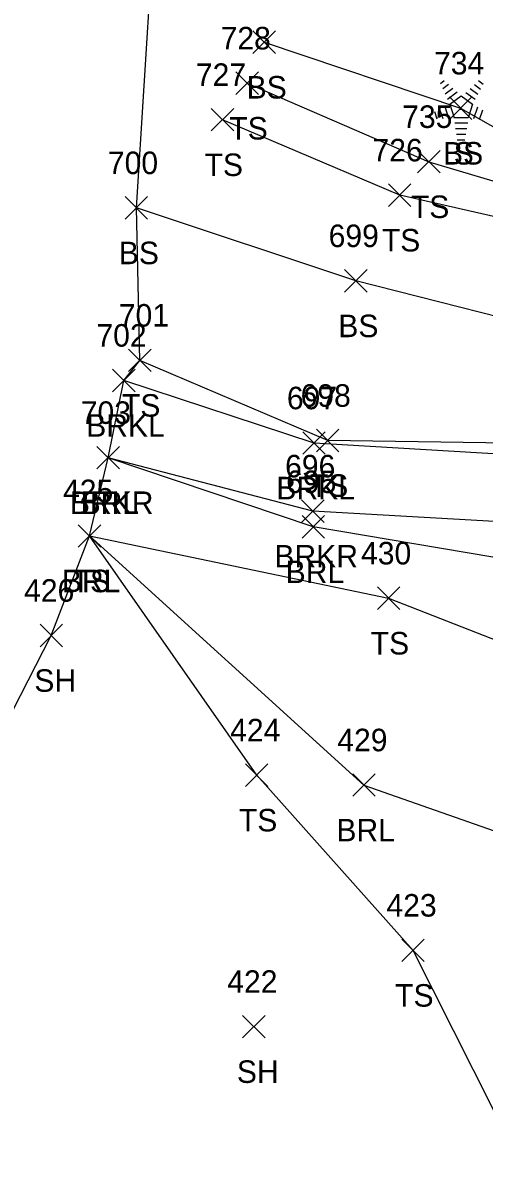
# Model space of a CAD drawing. Extents: x 1482574 to 1485769, y 580696 to 595649.
# Drawn here: x 1483551.5 to 1483592.5, y 584458.9 to 584560.7 of the extents above; entities that cross this region are included whole.
import ezdxf

# ---------------------------------------------------------------- set-up
doc = ezdxf.new("R2010")
doc.units = 0
for name, color, linetype in [('L_A', 7, 'Continuous'), ('L_I', 7, 'Continuous'), ('L_TIC', 7, 'Continuous'), ('LABL', 7, 'Continuous'), ('LAWE', 7, 'Continuous'), ('LELB', 7, 'Continuous'), ('LSOGP', 7, 'Continuous'), ('LTC', 7, 'Continuous')]:
    doc.layers.add(name, color=color, linetype=linetype)

msp = doc.modelspace()

# ---------------------------------------------------------------- linework, layer by layer
at = {"layer": 'L_TIC'}
for points in [[(1483571.91, 584558.01), (1483573.91, 584560.01)], [(1483573.91, 584558.01), (1483571.91, 584560.01)], [(1483570.4, 584554.37), (1483572.4, 584556.37)], [(1483572.4, 584554.37), (1483570.4, 584556.37)], [(1483589.37, 584552.15), (1483591.37, 584554.15)], [(1483591.37, 584552.15), (1483589.37, 584554.15)], [(1483568.2, 584551.13), (1483570.2, 584553.13)], [(1483570.2, 584551.13), (1483568.2, 584553.13)], [(1483586.54, 584547.4), (1483588.54, 584549.4)], [(1483588.54, 584547.4), (1483586.54, 584549.4)], [(1483583.96, 584544.43), (1483585.96, 584546.43)], [(1483585.96, 584544.43), (1483583.96, 584546.43)], [(1483560.55, 584543.3), (1483562.55, 584545.3)], [(1483562.55, 584543.3), (1483560.55, 584545.3)], [(1483580.06, 584536.82), (1483582.06, 584538.82)], [(1483582.06, 584536.82), (1483580.06, 584538.82)], [(1483560.86, 584529.76), (1483562.86, 584531.76)], [(1483562.86, 584529.76), (1483560.86, 584531.76)], [(1483559.44, 584527.98), (1483561.44, 584529.98)], [(1483561.44, 584527.98), (1483559.44, 584529.98)], [(1483576.34, 584522.42), (1483578.34, 584524.42)], [(1483578.34, 584522.42), (1483576.34, 584524.42)], [(1483577.56, 584522.64), (1483579.56, 584524.64)], [(1483579.56, 584522.64), (1483577.56, 584524.64)], [(1483558.05, 584521.12), (1483560.05, 584523.12)], [(1483560.05, 584521.12), (1483558.05, 584523.12)], [(1483558.05, 584521.12), (1483560.05, 584523.12)], [(1483560.05, 584521.12), (1483558.05, 584523.12)], [(1483576.23, 584516.37), (1483578.23, 584518.37)], [(1483578.23, 584516.37), (1483576.23, 584518.37)], [(1483556.39, 584514.17), (1483558.39, 584516.17)], [(1483558.39, 584514.17), (1483556.39, 584516.17)], [(1483556.39, 584514.17), (1483558.39, 584516.17)], [(1483558.39, 584514.17), (1483556.39, 584516.17)], [(1483576.28, 584514.98), (1483578.28, 584516.98)], [(1483578.28, 584514.98), (1483576.28, 584516.98)], [(1483582.97, 584508.64), (1483584.97, 584510.64)], [(1483584.97, 584508.64), (1483582.97, 584510.64)], [(1483552.99, 584505.33), (1483554.99, 584507.33)], [(1483554.99, 584505.33), (1483552.99, 584507.33)], [(1483571.25, 584492.93), (1483573.25, 584494.93)], [(1483573.25, 584492.93), (1483571.25, 584494.93)], [(1483580.78, 584492.05), (1483582.78, 584494.05)], [(1483582.78, 584492.05), (1483580.78, 584494.05)], [(1483585.14, 584477.37), (1483587.14, 584479.37)], [(1483587.14, 584477.37), (1483585.14, 584479.37)], [(1483570.99, 584470.6), (1483572.99, 584472.6)], [(1483572.99, 584470.6), (1483570.99, 584472.6)]]:
    msp.add_lwpolyline(points, dxfattribs=at)
at = {"layer": 'LABL'}
msp.add_lwpolyline([(1483557.39, 584515.17), (1483581.78, 584493.05), (1483599.69, 584486.77), (1483608.92, 584481.67), (1483619.05, 584468.28), (1483625.02, 584474.55), (1483629.48, 584489.33), (1483618.1, 584499.64), (1483610.75, 584504.98), (1483600.07, 584512.14), (1483577.28, 584515.98), (1483559.05, 584522.12)], dxfattribs=at)
at = {"layer": 'LAWE'}
for points in [[(1483652.51, 584466.2), (1483653.53, 584467.41), (1483653.05, 584476.59), (1483653.01, 584478.17), (1483649.99, 584483.79), (1483642.93, 584484.47), (1483640.94, 584492.97), (1483631.02, 584507.81), (1483619.15, 584517.04), (1483599.76, 584522.09), (1483577.34, 584523.42), (1483560.44, 584528.98)], [(1483652.51, 584466.2), (1483646.8, 584466.64), (1483640.31, 584474.56), (1483640.49, 584478.75), (1483634.5, 584491.43), (1483626.96, 584504.99), (1483616.49, 584511.47), (1483599.63, 584516.1), (1483577.23, 584517.37), (1483559.05, 584522.12)]]:
    msp.add_lwpolyline(points, dxfattribs=at)
at = {"layer": 'LELB'}
for points in [[(1483572.91, 584559.01), (1483590.37, 584553.15), (1483602.33, 584546.39), (1483621.48, 584539.15), (1483639.36, 584535.1), (1483650.65, 584535.66), (1483654.1, 584540.8)], [(1483571.4, 584555.37), (1483587.54, 584548.4), (1483600.81, 584544.44), (1483620.27, 584537.48), (1483638.06, 584531.53), (1483653.65, 584530.37)], [(1483660.89, 584522.88), (1483654.46, 584522.1), (1483632.32, 584529.86), (1483619.03, 584534.98), (1483601.24, 584541.74), (1483584.96, 584545.43), (1483569.2, 584552.13)], [(1483642.86, 584494.36), (1483642.41, 584507.25), (1483639.27, 584519), (1483618.28, 584527.02), (1483601.35, 584532.66), (1483581.06, 584537.82), (1483561.55, 584544.3)], [(1483644.29, 584485.9), (1483642.86, 584494.36), (1483632.83, 584509.64), (1483619.5, 584519.27), (1483600.64, 584523.33), (1483578.56, 584523.64), (1483561.86, 584530.76)], [(1483591.92, 584433.46), (1483595.11, 584460.63), (1483586.14, 584478.37), (1483572.25, 584493.93), (1483557.39, 584515.17), (1483583.97, 584509.64), (1483602.83, 584502.28), (1483610.56, 584496.52), (1483619.15, 584480.42), (1483625.02, 584474.55), (1483634.32, 584468.37), (1483637.97, 584475.16), (1483639.65, 584476.34), (1483633.45, 584491.23), (1483625.87, 584504.07), (1483614.94, 584508.57), (1483600.07, 584512.14)]]:
    msp.add_lwpolyline(points, dxfattribs=at)
at = {"layer": 'LSOGP'}
msp.add_lwpolyline([(1483388.16, 584341.61), (1483433.71, 584354.46), (1483482.76, 584376.06), (1483527.86, 584391.3), (1483563.77, 584397.36), (1483558.98, 584416.01), (1483534.08, 584453.69), (1483537.53, 584474.23), (1483553.99, 584506.33), (1483557.39, 584515.17), (1483559.05, 584522.12), (1483560.44, 584528.98), (1483561.86, 584530.76), (1483561.55, 584544.3), (1483564.3, 584587.66), (1483575.13, 584592.43), (1483575.16, 584618.73), (1483575, 584651.74), (1483601.74, 584679.59), (1483603.48, 584697.36), (1483598.5, 584707.5), (1483599.84, 584739.53), (1483601.86, 584774.6)], dxfattribs=at)
at = {"layer": 'LTC'}
for p, q in [((1483588.57, 584555.36), (1483588.92, 584555.62)), ((1483588.78, 584554.89), (1483589.31, 584555.28)), ((1483588.99, 584554.43), (1483589.69, 584554.94)), ((1483591.23, 584554.9), (1483591.9, 584554.41)), ((1483591.6, 584555.25), (1483592.15, 584554.85)), ((1483591.97, 584555.6), (1483592.39, 584555.29)), ((1483589.2, 584553.96), (1483590.08, 584554.6)), ((1483589.42, 584553.51), (1483590.43, 584554.24)), ((1483590.43, 584554.24), (1483591.43, 584553.52)), ((1483590.85, 584554.55), (1483591.66, 584553.96)), ((1483588.06, 584552.85), (1483588.27, 584552.2)), ((1483588.51, 584553.07), (1483588.78, 584552.24)), ((1483588.97, 584553.29), (1483589.3, 584552.27)), ((1483589.42, 584553.51), (1483589.81, 584552.31)), ((1483591.43, 584553.52), (1483591.04, 584552.31)), ((1483591.87, 584553.24), (1483591.53, 584552.21)), ((1483592.31, 584552.99), (1483592.03, 584552.11)), ((1483587.6, 584552.64), (1483587.75, 584552.17)), ((1483591.04, 584552.31), (1483589.81, 584552.31)), ((1483591, 584551.81), (1483589.86, 584551.81)), ((1483590.92, 584551.31), (1483589.93, 584551.31)), ((1483590.83, 584550.81), (1483590, 584550.81)), ((1483590.75, 584550.31), (1483590.08, 584550.31))]:
    msp.add_line(p, q, dxfattribs=at)

# ---------------------------------------------------------------- texts
at = {"layer": 'L_A'}
for s, p in [('BS', (1483571.35, 584554.01)), ('TS', (1483569.81, 584550.37)), ('BS', (1483588.81, 584548.15)), ('S', (1483589.76, 584548.15)), ('TS', (1483567.61, 584547.13)), ('TS', (1483585.95, 584543.4)), ('TS', (1483583.37, 584540.43)), ('BS', (1483559.99, 584539.3)), ('BS', (1483579.5, 584532.82)), ('TS', (1483560.27, 584525.76)), ('BRKL', (1483557.09, 584523.98)), ('BRKL', (1483573.99, 584518.42)), ('TS', (1483576.97, 584518.64)), ('BRKR', (1483555.64, 584517.12)), ('BRL', (1483556.59, 584517.12)), ('BRKR', (1483573.82, 584512.37)), ('BRL', (1483574.82, 584510.98)), ('BRL', (1483554.93, 584510.17)), ('TS', (1483555.8, 584510.17)), ('TS', (1483582.38, 584504.64)), ('SH', (1483552.48, 584501.33)), ('TS', (1483570.66, 584488.93)), ('BRL', (1483579.33, 584488.05)), ('TS', (1483584.55, 584473.37)), ('SH', (1483570.48, 584466.6))]:
    msp.add_text(s, height=2, dxfattribs=at).set_placement(p)
at = {"layer": 'L_I'}
for s, p in [('728', (1483569.04, 584558.37)), ('734', (1483588.01, 584556.15)), ('734', (1483588.01, 584556.15)), ('727', (1483566.84, 584555.13)), ('735', (1483585.18, 584551.4)), ('726', (1483582.54, 584548.43)), ('700', (1483559.02, 584547.3)), ('699', (1483578.64, 584540.82)), ('701', (1483559.99, 584533.76)), ('702', (1483558, 584531.98)), ('697', (1483574.93, 584526.42)), ('698', (1483576.15, 584526.64)), ('703', (1483556.61, 584525.12)), ('703', (1483556.61, 584525.12)), ('696', (1483574.77, 584520.37)), ('425', (1483555.03, 584518.17)), ('425', (1483555.03, 584518.17)), ('695', (1483574.87, 584518.98)), ('430', (1483581.52, 584512.64)), ('426', (1483551.57, 584509.33)), ('424', (1483569.89, 584496.93)), ('429', (1483579.41, 584496.05)), ('423', (1483583.78, 584481.37)), ('422', (1483569.63, 584474.6))]:
    msp.add_text(s, height=2, dxfattribs=at).set_placement(p)
at = {"layer": 'LTC'}
msp.add_text('.', height=1.04, rotation=270, dxfattribs=at).set_placement((1483590.32, 584553.25))

doc.saveas('drawing.dxf')
